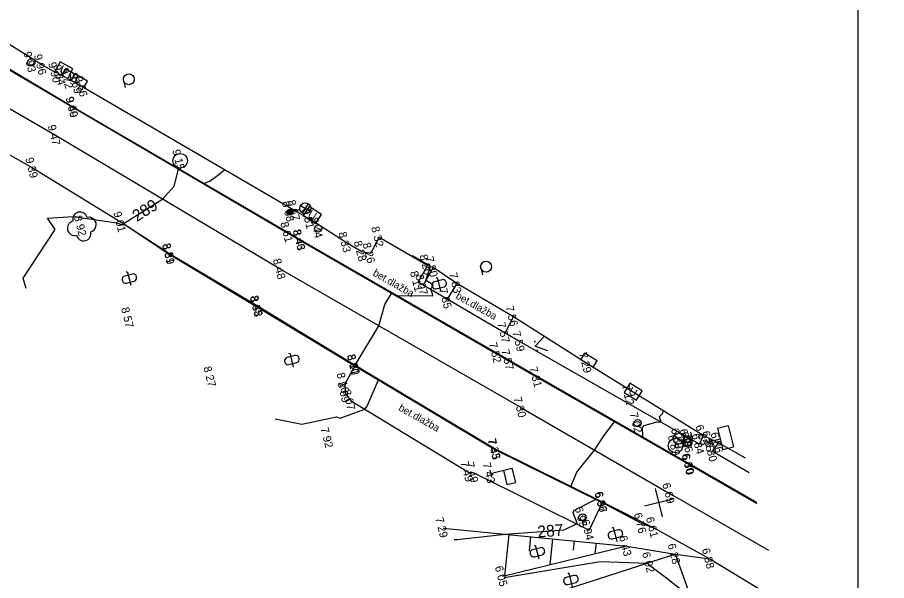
# Model space of a CAD drawing. Extents: x -740053 to -737517, y -1033516 to -1032488.
# Drawn here: x -739046.7 to -738987.3, y -1032628.5 to -1032590 of the extents above; entities that cross this region are included whole.
import ezdxf

# ---------------------------------------------------------------- set-up
doc = ezdxf.new("R2010")
doc.units = 0
for name, color, linetype in [('bod-oznac', 7, 'Continuous'), ('bod-vyska', 7, 'Continuous'), ('bod-vyska100', 7, 'Continuous'), ('chodnik', 7, 'Continuous'), ('Contours', 7, 'Continuous'), ('Contours text', 7, 'Continuous'), ('ctv-sit', 7, 'Continuous'), ('dopr-zariz', 7, 'Continuous'), ('el-zariz', 7, 'Continuous'), ('nazvy-bud-povr', 7, 'Continuous'), ('objekty-na-kanalizaci', 7, 'Continuous'), ('objekty-na-plynovodu', 7, 'Continuous'), ('objekty-na-vodovodu', 7, 'Continuous'), ('obrubnik', 7, 'Continuous'), ('osa-komunikace', 7, 'Continuous'), ('ploty', 7, 'Continuous'), ('Ploty-Vjezd', 7, 'Continuous'), ('podezdivka', 7, 'Continuous'), ('promika-formát', 7, 'Continuous'), ('Rozhrani-ploch', 7, 'Continuous'), ('silnice', 7, 'Continuous'), ('Technické šrafy', 7, 'Continuous'), ('Terenni-hrana', 7, 'Continuous'), ('Znacky-kultury', 7, 'Continuous')]:
    doc.layers.add(name, color=color, linetype=linetype)

# ---------------------------------------------------------------- blocks, each defined once
blk = doc.blocks.new('d_tabule')
for p, q in [((-1.5, 1.5), (-1.5, 3)), ((-1.5, 3), (1.5, 3)), ((1.5, 1.5), (1.5, 3)), ((-1.5, 1.5), (1.5, 1.5)), ((0, 0), (0, 1.5)), ((-0.5, 0), (0.5, 0))]:
    blk.add_line(p, q)
blk = doc.blocks.new('vo_soupe')
blk.add_circle((0, 0), 0.5)
blk = doc.blocks.new('po_kansa')
blk.add_circle((0, 0), 1)
blk = doc.blocks.new('po_sasou')
for p, q in [((-1.05, 0.76), (-1.05, -0.73)), ((0.95, 0.76), (-1.05, 0.76)), ((0.95, -0.73), (0.95, 0.76)), ((-1.05, -0.73), (0.95, -0.73))]:
    blk.add_line(p, q)
blk.add_text('U', height=1.09).set_placement((-0.58, -0.53))
blk = doc.blocks.new('el_rozd')
for p, q in [((-1, 1), (-1, 0)), ((1, 1), (-1, 1)), ((-1, 0), (1, 0)), ((1, 0), (1, 1))]:
    blk.add_line(p, q)
blk = doc.blocks.new('po_hydpo')
for p, q in [((-0.5, 1.76), (0.5, 1.76)), ((0, 0.75), (0, 1.76)), ((-0.56, -0.5), (0.56, 0.5))]:
    blk.add_line(p, q)
blk.add_circle((0, 0), 0.75)
blk = doc.blocks.new('el_lamst')
for p, q in [((-0.53, 1.66), (0.53, 2.72)), ((-0.53, 2.72), (0.53, 1.66)), ((0, 1.44), (0, 0.4))]:
    blk.add_line(p, q)
for centre, radius in [((0, 2.19), 0.75), ((0, 0), 0.4), ((0, 0), 0.351), ((0, 0), 0.305), ((0, 0), 0.305), ((0, 0), 0.26), ((0, 0), 0.206), ((0, 0), 0.161), ((0, 0), 0.115), ((0, 0), 0.0619)]:
    blk.add_circle(centre, radius)
blk = doc.blocks.new('POINT_DISPLAY')
blk.add_line((0, 0), (0, 0))
blk = doc.blocks.new('p_strom')
for centre, start, end in [((0, 1), 0, 180), ((-1, 0), 90, 270), ((1, 0), 270, 90), ((0, -1), 180, 0)]:
    blk.add_arc(centre, 1, start, end)
at = {"rotation": -180}
blk.add_blockref('POINT_DISPLAY', (0, 0), dxfattribs=at)
blk = doc.blocks.new('d_zast')
for p, q in [((0, 0), (0, 3)), ((0, 3), (2, 3)), ((2, 1.8), (2, 3)), ((0, 1.8), (2, 1.8)), ((-0.5, 0), (0.5, 0))]:
    blk.add_line(p, q)
blk = doc.blocks.new('pl_soupe')
blk.add_circle((0, 0), 0.5)
blk = doc.blocks.new('p_neplod')
for p, q in [((-0.82, 0), (-0.99, -0.18)), ((1, 0), (-0.82, 0)), ((-0.49, 0.56), (-0.49, -0.55)), ((0.05, 1.01), (-0.04, 1.01)), ((0.5, -0.55), (0.5, 0.56)), ((-0.04, -1), (0.05, -1))]:
    blk.add_line(p, q)
for centre, start, end in [((-0.04, 0.56), 90, 180), ((0.05, 0.56), 0, 90), ((-0.04, -0.55), 180, 270), ((0.05, -0.55), 270, 0)]:
    blk.add_arc(centre, 0.45, start, end)
blk = doc.blocks.new('p_park')
for p, q in [((-1, 1.5), (0, 0)), ((0, 0), (1, 1.5))]:
    blk.add_line(p, q)
for centre, start, end in [((-0.62, 0.1), 360, 180), ((-0.62, 0.1), 180, 360), ((0.66, 0.1), 0, 180), ((0.66, 0.1), 180, 0)]:
    blk.add_arc(centre, 0.05, start, end)
blk = doc.blocks.new('p_zahr')
blk.add_line((0, -0.75), (0.99, -0.75))
blk.add_circle((0, 0), 0.75)
blk = doc.blocks.new('ctvsit')
for p, q in [((0, -2), (0, 2)), ((2, 0), (-2, 0))]:
    blk.add_line(p, q)

msp = doc.modelspace()

# ---------------------------------------------------------------- linework, layer by layer
at = {"layer": 'chodnik'}
for p, q in [((-739042.865, -1032596.205), (-739049.498, -1032592.265)), ((-739028.188, -1032604.781), (-739042.865, -1032596.205)), ((-739027.331, -1032605.277), (-739028.188, -1032604.781)), ((-739013.928, -1032613.009), (-739027.331, -1032605.277)), ((-739017.327, -1032609.296), (-739018.956, -1032608.356)), ((-739013.355, -1032611.638), (-739017.327, -1032609.296)), ((-739012.328, -1032612.235), (-739013.355, -1032611.638)), ((-739000.064, -1032619.212), (-739012.328, -1032612.235)), ((-739013.085, -1032613.488), (-739013.928, -1032613.009)), ((-739013.085, -1032613.488), (-739000.743, -1032620.569)), ((-739023.63, -1032613.874), (-739024.329, -1032615.112)), ((-739023.63, -1032613.874), (-739014.007, -1032619.618)), ((-739024.329, -1032615.112), (-739024.292, -1032615.711)), ((-739024.292, -1032615.711), (-739023.922, -1032616.237)), ((-739023.922, -1032616.237), (-739015.862, -1032621.137)), ((-738999.81, -1032618.622), (-739000.064, -1032619.212)), ((-738999.18, -1032619.732), (-738998.776, -1032619.125)), ((-739014.007, -1032619.618), (-739006.717, -1032623.218)), ((-738996.664, -1032621.178), (-738999.18, -1032619.732)), ((-738996.151, -1032623.217), (-739000.743, -1032620.569)), ((-739015.862, -1032621.137), (-739015.498, -1032621.19)), ((-739015.498, -1032621.19), (-739007.616, -1032625.094)), ((-739006.717, -1032623.218), (-739007.616, -1032625.094))]:
    msp.add_line(p, q, dxfattribs=at)
at = {"layer": 'Contours'}
for points in [[(-739046.117, -1032608.581), (-739046.311, -1032607.865), (-739044.123, -1032604.543), (-739044.648, -1032603.775), (-739042.869, -1032603.657), (-739039.911, -1032604.08), (-739039.6, -1032604.197), (-739039.335, -1032604.233), (-739039.444, -1032604.157), (-739039.406, -1032604.109), (-739036.783, -1032602.47), (-739035.998, -1032601.586), (-739035.698, -1032600.427), (-739034.7, -1032600.987), (-739033.97, -1032601.403), (-739033.524, -1032601.217), (-739033.184, -1032600.968), (-739033.114, -1032600.921), (-739032.541, -1032600.46)], [(-739029.08, -1032617.485), (-739027.27, -1032617.861), (-739024.899, -1032617.354), (-739024.63, -1032617.44), (-739022.949, -1032616.828), (-739022.803, -1032616.618), (-739022.026, -1032614.831), (-739022.27, -1032614.677), (-739023.604, -1032613.816), (-739021.999, -1032611.128), (-739021.593, -1032609.666), (-739021.127, -1032608.911), (-739021.002, -1032608.954), (-739020.772, -1032609.061), (-739018.309, -1032609.07), (-739018.316, -1032608.948), (-739018.437, -1032608.655), (-739018.285, -1032608.322), (-739018.779, -1032608.038), (-739018.472, -1032607.063), (-739019.698, -1032606.344)], [(-739016.845, -1032625.739), (-739016.64, -1032625.728), (-739013.357, -1032625.37), (-739009.327, -1032625.07), (-739008.476, -1032624.668), (-739008.441, -1032624.621), (-739008.717, -1032623.914), (-739008.656, -1032623.766), (-739007.173, -1032622.993), (-739007.323, -1032622.914), (-739008.861, -1032622.104), (-739008.452, -1032621.13), (-739007.239, -1032619.624), (-739006.617, -1032618.64), (-739005.872, -1032617.703), (-739004.827, -1032618.257), (-739003.949, -1032618.73), (-739003.975, -1032618.045), (-739003.9, -1032618.027), (-739003.866, -1032617.955), (-739003.847, -1032617.941), (-739002.976, -1032617.697), (-739002.68, -1032617.724), (-739002.793, -1032617.336), (-739002.604, -1032617.126), (-739002.522, -1032616.943)], [(-739013.426, -1032628.333), (-739006.85, -1032627.241), (-739003.603, -1032627.363), (-739003.577, -1032627.422), (-739002.29, -1032628.383), (-739000.652, -1032629.669), (-739000.453, -1032629.769), (-738999.882, -1032629.944), (-738998.907, -1032630.135), (-738997.613, -1032630.29), (-738997.293, -1032630.353), (-738997.182, -1032630.369), (-738993.934, -1032632.025)]]:
    msp.add_lwpolyline(points, dxfattribs=at)
at = {"layer": 'obrubnik'}
for p, q in [((-739039.612, -1032604.048), (-739036.281, -1032606.262)), ((-739036.281, -1032606.262), (-739030.282, -1032609.856)), ((-739030.282, -1032609.856), (-739023.63, -1032613.874)), ((-739006.717, -1032623.218), (-739004.02, -1032624.632)), ((-739004.02, -1032624.632), (-739003.193, -1032624.929))]:
    msp.add_line(p, q, dxfattribs=at)
at = {"layer": 'osa-komunikace'}
for p, q in [((-739044.094, -1032598.123), (-739051.644, -1032593.775)), ((-739028.693, -1032607.28), (-739044.094, -1032598.123)), ((-739012.236, -1032616.739), (-739028.693, -1032607.28)), ((-739012.236, -1032616.739), (-739002.076, -1032622.606)), ((-738995.329, -1032626.484), (-739002.076, -1032622.606))]:
    msp.add_line(p, q, dxfattribs=at)
at = {"layer": 'ploty'}
msp.add_line((-739016.654, -1032608.24), (-739018.274, -1032607.132), dxfattribs=at)
at = {"layer": 'Ploty-Vjezd'}
for p, q in [((-739023.163, -1032606.063), (-739024.214, -1032605.451)), ((-739018.669, -1032606.995), (-739021.976, -1032605.084)), ((-739012.794, -1032610.507), (-739016.654, -1032608.24))]:
    msp.add_line(p, q, dxfattribs=at)
msp.add_lwpolyline([(-739044.07, -1032593.837), (-739045.041, -1032593.298), (-739048.663, -1032591.034)], dxfattribs=at)
at = {"layer": 'podezdivka'}
for p, q in [((-739027.698, -1032603.286), (-739042.227, -1032594.807)), ((-739026.724, -1032603.835), (-739027.698, -1032603.286)), ((-739024.214, -1032605.451), (-739026.724, -1032603.835)), ((-739021.976, -1032605.084), (-739022.563, -1032606.191)), ((-739022.563, -1032606.191), (-739023.163, -1032606.063)), ((-739019.313, -1032608.167), (-739018.669, -1032606.995)), ((-739018.274, -1032607.132), (-739018.956, -1032608.356)), ((-739018.956, -1032608.356), (-739019.313, -1032608.167)), ((-739007.764, -1032613.695), (-739012.794, -1032610.507)), ((-738999.81, -1032618.622), (-739007.764, -1032613.695)), ((-738998.776, -1032619.125), (-738999.81, -1032618.622)), ((-738996.916, -1032620.179), (-738998.776, -1032619.125))]:
    msp.add_line(p, q, dxfattribs=at)
at = {"layer": 'promika-formát'}
msp.add_lwpolyline([(-738989.249, -1032654.978), (-738884.249, -1032654.978), (-738884.249, -1032506.478), (-738989.249, -1032506.478)], close=True, dxfattribs=at)
at = {"layer": 'Rozhrani-ploch'}
for p, q in [((-739016.654, -1032608.24), (-739017.327, -1032609.296)), ((-739013.355, -1032611.638), (-739012.794, -1032610.507)), ((-739000.538, -1032629.984), (-739001.708, -1032626.731))]:
    msp.add_line(p, q, dxfattribs=at)
at = {"layer": 'silnice'}
for p, q in [((-739042.882, -1032596.22), (-739049.539, -1032592.306)), ((-739027.34, -1032605.321), (-739042.882, -1032596.22)), ((-739048.027, -1032599.01), (-739045.626, -1032600.354)), ((-739045.626, -1032600.354), (-739039.612, -1032604.048)), ((-739039.612, -1032604.048), (-739036.247, -1032606.233)), ((-739011.158, -1032614.673), (-739027.34, -1032605.321)), ((-739036.247, -1032606.233), (-739030.246, -1032609.795)), ((-739030.246, -1032609.795), (-739023.604, -1032613.816)), ((-739023.604, -1032613.816), (-739013.987, -1032619.572)), ((-739000.758, -1032620.635), (-739011.158, -1032614.673)), ((-739013.987, -1032619.572), (-739006.686, -1032623.179)), ((-738996.131, -1032623.296), (-739000.758, -1032620.635)), ((-739006.686, -1032623.179), (-739003.193, -1032624.929)), ((-739003.193, -1032624.929), (-738999.369, -1032627.05)), ((-739001.708, -1032626.731), (-739003.458, -1032627.316)), ((-739001.708, -1032626.731), (-738999.369, -1032627.05)), ((-739003.458, -1032627.316), (-739011.375, -1032629.866)), ((-738999.369, -1032627.05), (-738995.065, -1032629.648))]:
    msp.add_line(p, q, dxfattribs=at)
at = {"layer": 'Technické šrafy'}
for p, q in [((-739013.114, -1032625.394), (-739013.392, -1032628.23)), ((-739011.621, -1032625.54), (-739011.718, -1032626.535)), ((-739010.128, -1032625.686), (-739010.303, -1032627.475)), ((-739008.635, -1032625.833), (-739008.697, -1032626.465)), ((-739007.142, -1032625.979), (-739007.215, -1032626.72))]:
    msp.add_line(p, q, dxfattribs=at)
at = {"layer": 'Terenni-hrana'}
for p, q in [((-739017.592, -1032624.955), (-739005.032, -1032626.186)), ((-739005.032, -1032626.186), (-739013.522, -1032628.261)), ((-739005.032, -1032626.186), (-739001.708, -1032626.731))]:
    msp.add_line(p, q, dxfattribs=at)

# ---------------------------------------------------------------- block references
at = {"layer": 'bod-oznac', "rotation": -75.86979040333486}
for p in [(-739045.757, -1032593.117), (-739045.041, -1032593.298), (-739044.07, -1032593.837), (-739043.728, -1032594.009), (-739043.225, -1032594.244), (-739042.601, -1032594.592), (-739042.227, -1032594.807), (-739042.882, -1032596.22), (-739042.865, -1032596.205), (-739044.094, -1032598.123), (-739035.576, -1032599.846), (-739045.626, -1032600.354), (-739028.081, -1032603.362), (-739027.698, -1032603.286), (-739042.304, -1032604.334), (-739039.612, -1032604.048), (-739026.724, -1032603.835), (-739028.188, -1032604.781), (-739026.151, -1032604.475), (-739027.34, -1032605.321), (-739027.331, -1032605.277), (-739024.214, -1032605.451), (-739021.976, -1032605.084), (-739023.163, -1032606.063), (-739036.281, -1032606.262), (-739036.247, -1032606.233), (-739022.563, -1032606.191), (-739028.693, -1032607.28), (-739018.669, -1032606.995), (-739018.274, -1032607.132), (-739019.313, -1032608.167), (-739018.956, -1032608.356), (-739016.654, -1032608.24), (-739017.327, -1032609.296), (-739030.282, -1032609.856), (-739030.246, -1032609.795), (-739039.075, -1032610.605), (-739012.794, -1032610.507), (-739013.355, -1032611.638), (-739012.328, -1032612.235), (-739013.928, -1032613.009), (-739023.604, -1032613.816), (-739013.085, -1032613.488), (-739007.764, -1032613.695), (-739023.63, -1032613.874), (-739033.449, -1032614.644), (-739011.158, -1032614.673), (-739024.329, -1032615.112), (-739024.292, -1032615.711), (-739004.84, -1032615.929), (-739023.922, -1032616.237), (-739012.236, -1032616.739), (-739004.298, -1032617.793), (-739025.439, -1032618.815), (-739001.486, -1032618.848), (-739000.916, -1032618.901), (-739000.833, -1032619.107), (-738999.81, -1032618.622), (-738999.375, -1032619.039), (-738998.776, -1032619.125), (-739014.007, -1032619.618), (-739013.987, -1032619.572), (-739001.708, -1032619.317), (-739000.064, -1032619.212), (-738999.18, -1032619.732), (-739000.758, -1032620.635), (-739000.743, -1032620.569), (-739015.862, -1032621.137), (-739015.498, -1032621.19), (-739014.353, -1032621.232), (-739002.076, -1032622.606), (-739006.717, -1032623.218), (-739006.686, -1032623.179), (-739008.062, -1032624.226), (-739017.592, -1032624.955), (-739007.616, -1032625.094), (-739004.02, -1032624.632), (-739003.193, -1032624.929), (-739005.032, -1032626.186), (-739001.708, -1032626.731), (-739003.458, -1032627.316), (-738999.369, -1032627.05), (-739013.522, -1032628.261)]:
    msp.add_blockref('POINT_DISPLAY', p, dxfattribs=at)
at = {"layer": 'ctv-sit', "xscale": 0.49999999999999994, "yscale": 0.5, "rotation": 104.13020959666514}
msp.add_blockref('ctvsit', (-739002.861, -1032623.216), dxfattribs=at)
at = {"layer": 'dopr-zariz', "xscale": 0.49999999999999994, "yscale": 0.4999999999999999, "rotation": -75.86979040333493}
for name, p in [('d_tabule', (-738999.375, -1032619.039)), ('d_zast', (-739014.353, -1032621.232))]:
    msp.add_blockref(name, p, dxfattribs=at)
at = {"layer": 'el-zariz'}
for name, p, xscale, yscale, rotation in [('el_rozd', (-739043.225, -1032594.244), 0.4999999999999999, 0.4999999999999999, -29.45536719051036), ('el_rozd', (-739042.601, -1032594.592), 0.49999999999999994, 0.4999999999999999, -29.93059944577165), ('el_lamst', (-739028.081, -1032603.362), 0.49999999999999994, 0.4999999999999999, -75.86979040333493), ('el_rozd', (-739007.764, -1032613.695), 0.5, 0.49999999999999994, -31.77917085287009)]:
    msp.add_blockref(name, p, dxfattribs=dict(at, xscale=xscale, yscale=yscale, rotation=rotation))
at = {"layer": 'objekty-na-kanalizaci', "xscale": 0.49999999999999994, "yscale": 0.4999999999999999, "rotation": -75.86979040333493}
for p in [(-739035.576, -1032599.846), (-739001.708, -1032619.317)]:
    msp.add_blockref('po_kansa', p, dxfattribs=at)
at = {"layer": 'objekty-na-plynovodu'}
for name, p, xscale, yscale, rotation in [('po_sasou', (-739043.506, -1032593.669), 0.49999999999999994, 0.49999999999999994, -28.007385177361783), ('po_sasou', (-739026.523, -1032603.573), 0.4999999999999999, 0.4999999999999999, -32.769901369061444), ('po_sasou', (-739004.587, -1032615.657), 0.5, 0.4999999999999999, -31.534423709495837), ('pl_soupe', (-739008.062, -1032624.226), 0.49999999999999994, 0.4999999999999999, -75.86979040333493)]:
    msp.add_blockref(name, p, dxfattribs=dict(at, xscale=xscale, yscale=yscale, rotation=rotation))
at = {"layer": 'objekty-na-vodovodu', "xscale": 0.49999999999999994}
for name, p, yscale, rotation in [('vo_soupe', (-739045.757, -1032593.117), 0.4999999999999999, -75.86979040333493), ('vo_soupe', (-739026.151, -1032604.475), 0.4999999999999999, -75.86979040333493), ('vo_soupe', (-739004.298, -1032617.793), 0.4999999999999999, -75.86979040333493), ('po_hydpo', (-739001.486, -1032618.848), 0.5, -75.86979040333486), ('vo_soupe', (-739000.916, -1032618.901), 0.4999999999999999, -75.86979040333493), ('vo_soupe', (-739000.833, -1032619.107), 0.4999999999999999, -75.86979040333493)]:
    msp.add_blockref(name, p, dxfattribs=dict(at, yscale=yscale, rotation=rotation))
at = {"layer": 'Znacky-kultury', "xscale": 0.49999999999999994}
for name, p, yscale, rotation in [('p_zahr', (-739039.09, -1032594.271), 0.5, -75.86979040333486), ('p_strom', (-739042.304, -1032604.334), 0.4999999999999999, -75.86979040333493), ('p_zahr', (-739014.659, -1032607.083), 0.5, -75.86979040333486), ('p_neplod', (-739039.055, -1032607.895), 0.5, -75.86979040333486), ('p_neplod', (-739017.871, -1032608.284), 0.5, -75.86979040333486), ('p_park', (-739011.303, -1032612.518), 0.5, -75.86979040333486), ('p_neplod', (-739027.945, -1032613.473), 0.5, -75.86979040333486), ('p_neplod', (-739005.82, -1032625.384), 0.5, -75.86979040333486), ('p_neplod', (-739011.152, -1032626.603), 0.5, -75.86979040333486), ('p_neplod', (-739008.867, -1032628.499), 0.5, -75.86979040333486)]:
    msp.add_blockref(name, p, dxfattribs=dict(at, yscale=yscale, rotation=rotation))

# ---------------------------------------------------------------- texts
at = {"layer": 'bod-vyska'}
for s, p in [('9 93', (-739046.302, -1032592.455)), ('9 96', (-739045.586, -1032592.635)), ('9 90', (-739044.615, -1032593.175)), ('9 84', (-739044.273, -1032593.346)), ('9 72', (-739043.77, -1032593.581)), ('9 69', (-739043.15, -1032593.916)), ('9 66', (-739042.776, -1032594.131)), ('9 49', (-739043.427, -1032595.557)), ('9 60', (-739043.414, -1032595.529)), ('9 47', (-739044.639, -1032597.46)), ('9 15', (-739036.131, -1032599.145)), ('9 39', (-739046.171, -1032599.692)), ('8 67', (-739028.249, -1032602.598)), ('8 68', (-739028.632, -1032602.674)), ('8 51', (-739027.273, -1032603.16)), ('8 92', (-739042.852, -1032603.658)), ('9 01', (-739040.157, -1032603.385)), ('8 44', (-739026.699, -1032603.799)), ('8 61', (-739028.739, -1032604.093)), ('8 32', (-739022.524, -1032604.408)), ('8 43', (-739027.889, -1032604.645)), ('8 46', (-739027.879, -1032604.601)), ('8 33', (-739024.762, -1032604.776)), ('8 89', (-739036.829, -1032605.586)), ('8 81', (-739036.795, -1032605.557)), ('8 28', (-739023.711, -1032605.388)), ('8 26', (-739023.112, -1032605.515)), ('8 48', (-739029.241, -1032606.605)), ('8 20', (-739019.218, -1032606.319)), ('7 80', (-739018.822, -1032606.457)), ('8 11', (-739019.87, -1032607.453)), ('8 07', (-739019.504, -1032607.68)), ('7 83', (-739017.202, -1032607.565)), ('8 45', (-739030.794, -1032609.12)), ('7 85', (-739017.875, -1032608.621)), ('8 58', (-739030.83, -1032609.181)), ('8 57', (-739039.623, -1032609.93)), ('7 56', (-739013.342, -1032609.831)), ('7 57', (-739013.903, -1032610.962)), ('7 59', (-739012.876, -1032611.559)), ('7 52', (-739014.476, -1032612.333)), ('8 11', (-739024.188, -1032613.16)), ('8 00', (-739024.152, -1032613.14)), ('7 57', (-739013.633, -1032612.812)), ('7 29', (-739008.312, -1032613.019)), ('8 27', (-739033.997, -1032613.969)), ('8 10', (-739024.887, -1032614.398)), ('7 31', (-739011.706, -1032613.997)), ('8 09', (-739024.84, -1032615.035)), ('8 07', (-739024.47, -1032615.561)), ('7 12', (-739005.398, -1032615.215)), ('7 30', (-739012.784, -1032616.063)), ('7 02', (-739004.847, -1032617.117)), ('6 85', (-739000.352, -1032617.972)), ('7 92', (-739025.987, -1032618.139)), ('6 89', (-739002.25, -1032618.666)), ('6 89', (-739002.027, -1032618.198)), ('6 87', (-739001.457, -1032618.25)), ('6 86', (-739001.375, -1032618.456)), ('6 84', (-739000.606, -1032618.562)), ('6 85', (-738999.917, -1032618.389)), ('6 86', (-738999.318, -1032618.475)), ('7 45', (-739014.555, -1032618.943)), ('7 33', (-739014.535, -1032618.896)), ('6 80', (-738999.722, -1032619.082)), ('7 49', (-739016.41, -1032620.461)), ('6 70', (-739001.299, -1032619.984)), ('6 80', (-739001.285, -1032619.919)), ('7 49', (-739016.046, -1032620.514)), ('7 43', (-739014.901, -1032620.556)), ('6 69', (-739002.621, -1032621.943)), ('6 97', (-739007.259, -1032622.567)), ('6 86', (-739007.228, -1032622.529)), ('6 95', (-739008.603, -1032623.576)), ('6 76', (-739004.562, -1032623.982)), ('7 29', (-739018.14, -1032624.279)), ('6 94', (-739008.158, -1032624.444)), ('6 61', (-739003.738, -1032624.266)), ('6 43', (-739005.573, -1032625.536)), ('6 28', (-739002.25, -1032626.081)), ('6 38', (-738999.911, -1032626.4)), ('6 02', (-739004, -1032626.666)), ('6 05', (-739014.064, -1032627.611))]:
    msp.add_text(s, height=0.55, rotation=284.13021, dxfattribs=at).set_placement(p)
at = {"layer": 'bod-vyska100'}
for s, p in [('289 93', (-739045.83, -1032592.965)), ('289 96', (-739045.114, -1032593.146)), ('289 90', (-739044.143, -1032593.685)), ('289 84', (-739043.8, -1032593.856)), ('289 72', (-739043.298, -1032594.091)), ('289 69', (-739042.674, -1032594.438)), ('289 66', (-739042.301, -1032594.653)), ('289 49', (-739042.955, -1032596.067)), ('289 60', (-739042.939, -1032596.051)), ('289 47', (-739044.167, -1032597.97)), ('289 15', (-739035.65, -1032599.69)), ('289 39', (-739045.699, -1032600.202)), ('288 67', (-739027.771, -1032603.132)), ('288 68', (-739028.154, -1032603.207)), ('288 51', (-739026.797, -1032603.682)), ('288 92', (-739042.377, -1032604.18)), ('289 01', (-739039.685, -1032603.896)), ('288 44', (-739026.224, -1032604.321)), ('288 61', (-739028.261, -1032604.626)), ('288 32', (-739022.049, -1032604.93)), ('288 43', (-739027.413, -1032605.167)), ('288 46', (-739027.404, -1032605.123)), ('288 33', (-739024.287, -1032605.298)), ('288 89', (-739036.354, -1032606.108)), ('288 81', (-739036.32, -1032606.079)), ('288 28', (-739023.236, -1032605.91)), ('288 26', (-739022.636, -1032606.037)), ('288 48', (-739028.766, -1032607.126)), ('288 20', (-739018.742, -1032606.841)), ('287 80', (-739018.347, -1032606.978)), ('288 11', (-739019.387, -1032608.01)), ('288 07', (-739019.029, -1032608.202)), ('287 83', (-739016.727, -1032608.087)), ('288 45', (-739030.319, -1032609.642)), ('287 85', (-739017.4, -1032609.143)), ('288 58', (-739030.355, -1032609.702)), ('288 57', (-739039.148, -1032610.452)), ('287 56', (-739012.867, -1032610.353)), ('287 57', (-739013.428, -1032611.484)), ('287 59', (-739012.401, -1032612.081)), ('287 52', (-739014.001, -1032612.855)), ('288 11', (-739023.704, -1032613.717)), ('288 00', (-739023.677, -1032613.662)), ('287 57', (-739013.158, -1032613.334)), ('287 29', (-739007.837, -1032613.541)), ('288 27', (-739033.522, -1032614.49)), ('288 10', (-739024.403, -1032614.955)), ('287 31', (-739011.231, -1032614.519)), ('288 09', (-739024.365, -1032615.557)), ('288 07', (-739023.995, -1032616.083)), ('287 12', (-739004.914, -1032615.772)), ('287 30', (-739012.309, -1032616.585)), ('287 02', (-739004.371, -1032617.639)), ('286 85', (-738999.883, -1032618.469)), ('287 92', (-739025.512, -1032618.661)), ('286 89', (-739001.781, -1032619.163)), ('286 89', (-739001.559, -1032618.694)), ('286 87', (-739000.989, -1032618.747)), ('286 86', (-739000.906, -1032618.953)), ('286 84', (-739000.137, -1032619.058)), ('286 85', (-738999.448, -1032618.885)), ('286 86', (-738998.849, -1032618.971)), ('287 45', (-739014.08, -1032619.464)), ('287 33', (-739014.06, -1032619.418)), ('286 80', (-738999.253, -1032619.578)), ('287 49', (-739015.935, -1032620.983)), ('286 70', (-739000.831, -1032620.481)), ('286 80', (-739000.816, -1032620.415)), ('287 49', (-739015.571, -1032621.036)), ('287 43', (-739014.426, -1032621.078)), ('286 69', (-739002.15, -1032622.451)), ('286 97', (-739006.79, -1032623.064)), ('286 86', (-739006.759, -1032623.025)), ('286 95', (-739008.135, -1032624.073)), ('286 76', (-739004.093, -1032624.478)), ('287 29', (-739017.665, -1032624.801)), ('286 94', (-739007.69, -1032624.94)), ('286 61', (-739003.266, -1032624.774)), ('286 43', (-739005.105, -1032626.032)), ('286 28', (-739001.781, -1032626.577)), ('286 38', (-738999.443, -1032626.896)), ('286 02', (-739003.531, -1032627.162)), ('286 05', (-739013.595, -1032628.108))]:
    msp.add_text(s, height=0.05, rotation=284.13021, dxfattribs=at).set_placement(p)
at = {"layer": 'Contours text'}
for s, rotation, p in [('289', 31.98817, (-739038.539, -1032604.039)), ('287', 4.25738, (-739011.125, -1032625.605))]:
    msp.add_text(s, height=0.8, rotation=rotation, dxfattribs=at).set_placement(p)
at = {"layer": 'nazvy-bud-povr'}
for p in [(-739022.448, -1032607.658), (-739016.783, -1032609.22), (-739020.696, -1032616.875)]:
    msp.add_text('bet.dlažba', height=0.5, rotation=330.5345, dxfattribs=at).set_placement(p)

doc.saveas('drawing.dxf')
